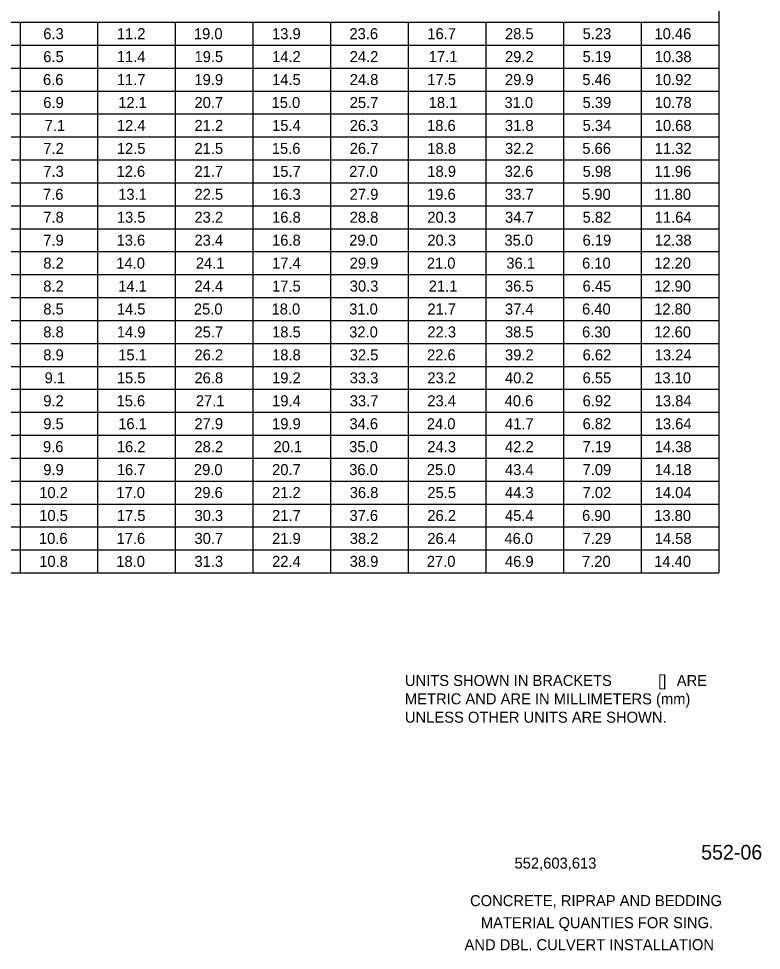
# Model space of a CAD drawing. Extents: x 49991.4 to 50047.6, y 49987.6 to 50011.4.
# Drawn here: x 50043.52 to 50047.57, y 49988.32 to 49993.4 of the extents above; entities that cross this region are included whole.
import ezdxf

# ---------------------------------------------------------------- set-up
doc = ezdxf.new("R2010")
doc.units = 0
doc.layers.add('Level 2', color=7, linetype='Continuous')

msp = doc.modelspace()

# ---------------------------------------------------------------- linework, layer by layer
at = {"layer": 'Level 2'}
for p, q in [((50047.3341, 49998.1607), (50047.3341, 49990.3807)), ((50039.4641, 49993.3807), (50047.3341, 49993.3807)), ((50043.5262, 49993.3807), (50043.5262, 49990.3807)), ((50043.9493, 49993.3807), (50043.9493, 49990.3807)), ((50044.3724, 49993.3807), (50044.3724, 49990.3807)), ((50044.7955, 49993.3807), (50044.7955, 49990.3807)), ((50045.2186, 49993.3807), (50045.2186, 49990.3807)), ((50045.6417, 49993.3807), (50045.6417, 49990.3807)), ((50046.0648, 49993.3807), (50046.0648, 49990.3807)), ((50046.4879, 49993.3807), (50046.4879, 49990.3807)), ((50046.911, 49993.3807), (50046.911, 49990.3807)), ((50039.4641, 49993.2557), (50047.3341, 49993.2557)), ((50039.4641, 49993.1307), (50047.3341, 49993.1307)), ((50039.4641, 49993.0057), (50047.3341, 49993.0057)), ((50039.4641, 49992.8807), (50047.3341, 49992.8807)), ((50039.4641, 49992.7557), (50047.3341, 49992.7557)), ((50039.4641, 49992.6307), (50047.3341, 49992.6307)), ((50039.4641, 49992.5057), (50047.3341, 49992.5057)), ((50039.4641, 49992.3807), (50047.3341, 49992.3807)), ((50039.4641, 49992.2557), (50047.3341, 49992.2557)), ((50039.4641, 49992.1307), (50047.3341, 49992.1307)), ((50039.4641, 49992.0057), (50047.3341, 49992.0057)), ((50039.4641, 49991.8807), (50047.3341, 49991.8807)), ((50039.4641, 49991.7557), (50047.3341, 49991.7557)), ((50039.4641, 49991.6307), (50047.3341, 49991.6307)), ((50039.4641, 49991.5057), (50047.3341, 49991.5057)), ((50039.4641, 49991.3807), (50047.3341, 49991.3807)), ((50039.4641, 49991.2557), (50047.3341, 49991.2557)), ((50039.4641, 49991.1307), (50047.3341, 49991.1307)), ((50039.4641, 49991.0057), (50047.3341, 49991.0057)), ((50039.4641, 49990.8807), (50047.3341, 49990.8807)), ((50039.4641, 49990.7557), (50047.3341, 49990.7557)), ((50039.4641, 49990.6307), (50047.3341, 49990.6307)), ((50039.4641, 49990.5057), (50047.3341, 49990.5057)), ((50039.4641, 49990.3807), (50047.3341, 49990.3807))]:
    msp.add_line(p, q, dxfattribs=at)

# ---------------------------------------------------------------- texts
for s, height, p in [(' 6.3', 0.06, (50043.6308, 49993.2882)), ('11.2', 0.06, (50044.0539, 49993.2882)), ('19.0', 0.06, (50044.474, 49993.2882)), ('13.9', 0.06, (50044.8999, 49993.2882)), ('23.6', 0.06, (50045.3216, 49993.2882)), ('16.7', 0.06, (50045.7463, 49993.2882)), ('28.5', 0.06, (50046.1694, 49993.2882)), ('5.23', 0.06, (50046.5925, 49993.2882)), ('10.46', 0.06, (50046.984, 49993.2882)), (' 6.5', 0.06, (50043.6308, 49993.1632)), ('11.4', 0.06, (50044.0539, 49993.1632)), ('19.5', 0.06, (50044.477, 49993.1632)), ('14.2', 0.06, (50044.9001, 49993.1632)), ('24.2', 0.06, (50045.3232, 49993.1632)), ('17.1', 0.06, (50045.7537, 49993.1632)), ('29.2', 0.06, (50046.1694, 49993.1632)), ('5.19', 0.06, (50046.5923, 49993.1632)), ('10.38', 0.06, (50046.9856, 49993.1632)), (' 6.6', 0.06, (50043.6292, 49993.0382)), ('11.7', 0.06, (50044.0539, 49993.0382)), ('19.9', 0.06, (50044.4768, 49993.0382)), ('14.5', 0.06, (50044.9001, 49993.0382)), ('24.8', 0.06, (50045.3232, 49993.0382)), ('17.5', 0.06, (50045.7463, 49993.0382)), ('29.9', 0.06, (50046.1692, 49993.0382)), ('5.46', 0.06, (50046.5909, 49993.0382)), ('10.92', 0.06, (50046.9856, 49993.0382)), (' 6.9', 0.06, (50043.6306, 49992.9132)), ('12.1', 0.06, (50044.0613, 49992.9132)), ('20.7', 0.06, (50044.477, 49992.9132)), ('15.0', 0.06, (50044.8971, 49992.9132)), ('25.7', 0.06, (50045.3232, 49992.9132)), ('18.1', 0.06, (50045.7537, 49992.9132)), ('31.0', 0.06, (50046.1664, 49992.9132)), ('5.39', 0.06, (50046.5923, 49992.9132)), ('10.78', 0.06, (50046.9856, 49992.9132)), (' 7.1', 0.06, (50043.6382, 49992.7882)), ('12.4', 0.06, (50044.0539, 49992.7882)), ('21.2', 0.06, (50044.477, 49992.7882)), ('15.4', 0.06, (50044.9001, 49992.7882)), ('26.3', 0.06, (50045.3232, 49992.7882)), ('18.6', 0.06, (50045.7447, 49992.7882)), ('31.8', 0.06, (50046.1694, 49992.7882)), ('5.34', 0.06, (50046.5925, 49992.7882)), ('10.68', 0.06, (50046.9856, 49992.7882)), (' 7.2', 0.06, (50043.6308, 49992.6632)), ('12.5', 0.06, (50044.0539, 49992.6632)), ('21.5', 0.06, (50044.477, 49992.6632)), ('15.6', 0.06, (50044.8985, 49992.6632)), ('26.7', 0.06, (50045.3232, 49992.6632)), ('18.8', 0.06, (50045.7463, 49992.6632)), ('32.2', 0.06, (50046.1694, 49992.6632)), ('5.66', 0.06, (50046.5909, 49992.6632)), ('11.32', 0.06, (50046.9856, 49992.6632)), (' 7.3', 0.06, (50043.6308, 49992.5382)), ('12.6', 0.06, (50044.0523, 49992.5382)), ('21.7', 0.06, (50044.477, 49992.5382)), ('15.7', 0.06, (50044.9001, 49992.5382)), ('27.0', 0.06, (50045.3202, 49992.5382)), ('18.9', 0.06, (50045.7461, 49992.5382)), ('32.6', 0.06, (50046.1678, 49992.5382)), ('5.98', 0.06, (50046.5925, 49992.5382)), ('11.96', 0.06, (50046.984, 49992.5382)), (' 7.6', 0.06, (50043.6292, 49992.4132)), ('13.1', 0.06, (50044.0613, 49992.4132)), ('22.5', 0.06, (50044.477, 49992.4132)), ('16.3', 0.06, (50044.9001, 49992.4132)), ('27.9', 0.06, (50045.323, 49992.4132)), ('19.6', 0.06, (50045.7447, 49992.4132)), ('33.7', 0.06, (50046.1694, 49992.4132)), ('5.90', 0.06, (50046.5895, 49992.4132)), ('11.80', 0.06, (50046.9826, 49992.4132)), (' 7.8', 0.06, (50043.6308, 49992.2882)), ('13.5', 0.06, (50044.0539, 49992.2882)), ('23.2', 0.06, (50044.477, 49992.2882)), ('16.8', 0.06, (50044.9001, 49992.2882)), ('28.8', 0.06, (50045.3232, 49992.2882)), ('20.3', 0.06, (50045.7463, 49992.2882)), ('34.7', 0.06, (50046.1694, 49992.2882)), ('5.82', 0.06, (50046.5925, 49992.2882)), ('11.64', 0.06, (50046.9856, 49992.2882)), (' 7.9', 0.06, (50043.6306, 49992.1632)), ('13.6', 0.06, (50044.0523, 49992.1632)), ('23.4', 0.06, (50044.477, 49992.1632)), ('16.8', 0.06, (50044.9001, 49992.1632)), ('29.0', 0.06, (50045.3202, 49992.1632)), ('20.3', 0.06, (50045.7463, 49992.1632)), ('35.0', 0.06, (50046.1664, 49992.1632)), ('6.19', 0.06, (50046.5923, 49992.1632)), ('12.38', 0.06, (50046.9856, 49992.1632)), (' 8.2', 0.06, (50043.6308, 49992.0382)), ('14.0', 0.06, (50044.0509, 49992.0382)), ('24.1', 0.06, (50044.4844, 49992.0382)), ('29.9', 0.06, (50045.323, 49992.0382)), ('21.0', 0.06, (50045.7433, 49992.0382)), ('36.1', 0.06, (50046.1768, 49992.0382)), ('6.10', 0.06, (50046.5895, 49992.0382)), ('12.20', 0.06, (50046.9826, 49992.0382)), ('17.4', 0.06, (50044.9001, 49992.0382)), (' 8.2', 0.06, (50043.6308, 49991.9132)), ('14.1', 0.06, (50044.0613, 49991.9132)), ('24.4', 0.06, (50044.477, 49991.9132)), ('17.5', 0.06, (50044.9001, 49991.9132)), ('30.3', 0.06, (50045.3232, 49991.9132)), ('21.1', 0.06, (50045.7537, 49991.9132)), ('36.5', 0.06, (50046.1694, 49991.9132)), ('6.45', 0.06, (50046.5925, 49991.9132)), ('12.90', 0.06, (50046.9826, 49991.9132)), (' 8.5', 0.06, (50043.6308, 49991.7882)), ('14.5', 0.06, (50044.0539, 49991.7882)), ('25.0', 0.06, (50044.474, 49991.7882)), ('18.0', 0.06, (50044.8971, 49991.7882)), ('31.0', 0.06, (50045.3202, 49991.7882)), ('21.7', 0.06, (50045.7463, 49991.7882)), ('37.4', 0.06, (50046.1694, 49991.7882)), ('6.40', 0.06, (50046.5895, 49991.7882)), ('12.80', 0.06, (50046.9826, 49991.7882)), (' 8.8', 0.06, (50043.6308, 49991.6632)), ('14.9', 0.06, (50044.0537, 49991.6632)), ('25.7', 0.06, (50044.477, 49991.6632)), ('18.5', 0.06, (50044.9001, 49991.6632)), ('32.0', 0.06, (50045.3202, 49991.6632)), ('22.3', 0.06, (50045.7463, 49991.6632)), ('38.5', 0.06, (50046.1694, 49991.6632)), ('6.30', 0.06, (50046.5895, 49991.6632)), ('12.60', 0.06, (50046.9826, 49991.6632)), (' 8.9', 0.06, (50043.6306, 49991.5382)), ('15.1', 0.06, (50044.0613, 49991.5382)), ('26.2', 0.06, (50044.477, 49991.5382)), ('18.8', 0.06, (50044.9001, 49991.5382)), ('32.5', 0.06, (50045.3232, 49991.5382)), ('22.6', 0.06, (50045.7447, 49991.5382)), ('39.2', 0.06, (50046.1694, 49991.5382)), ('6.62', 0.06, (50046.5925, 49991.5382)), ('13.24', 0.06, (50046.9856, 49991.5382)), (' 9.1', 0.06, (50043.6382, 49991.4132)), ('15.5', 0.06, (50044.0539, 49991.4132)), ('26.8', 0.06, (50044.477, 49991.4132)), ('19.2', 0.06, (50044.9001, 49991.4132)), ('33.3', 0.06, (50045.3232, 49991.4132)), ('23.2', 0.06, (50045.7463, 49991.4132)), ('40.2', 0.06, (50046.1694, 49991.4132)), ('6.55', 0.06, (50046.5925, 49991.4132)), ('13.10', 0.06, (50046.9826, 49991.4132)), (' 9.2', 0.06, (50043.6308, 49991.2882)), ('15.6', 0.06, (50044.0523, 49991.2882)), ('27.1', 0.06, (50044.4844, 49991.2882)), ('19.4', 0.06, (50044.9001, 49991.2882)), ('33.7', 0.06, (50045.3232, 49991.2882)), ('23.4', 0.06, (50045.7463, 49991.2882)), ('40.6', 0.06, (50046.1678, 49991.2882)), ('6.92', 0.06, (50046.5925, 49991.2882)), ('13.84', 0.06, (50046.9856, 49991.2882)), (' 9.5', 0.06, (50043.6308, 49991.1632)), ('16.1', 0.06, (50044.0613, 49991.1632)), ('27.9', 0.06, (50044.4768, 49991.1632)), ('19.9', 0.06, (50044.8999, 49991.1632)), ('34.6', 0.06, (50045.3216, 49991.1632)), ('24.0', 0.06, (50045.7433, 49991.1632)), ('41.7', 0.06, (50046.1694, 49991.1632)), ('6.82', 0.06, (50046.5925, 49991.1632)), ('13.64', 0.06, (50046.9856, 49991.1632)), (' 9.6', 0.06, (50043.6292, 49991.0382)), ('16.2', 0.06, (50044.0539, 49991.0382)), ('28.2', 0.06, (50044.477, 49991.0382)), ('20.1', 0.06, (50044.9075, 49991.0382)), ('35.0', 0.06, (50045.3202, 49991.0382)), ('24.3', 0.06, (50045.7463, 49991.0382)), ('42.2', 0.06, (50046.1694, 49991.0382)), ('7.19', 0.06, (50046.5923, 49991.0382)), ('14.38', 0.06, (50046.9856, 49991.0382)), (' 9.9', 0.06, (50043.6306, 49990.9132)), ('16.7', 0.06, (50044.0539, 49990.9132)), ('29.0', 0.06, (50044.474, 49990.9132)), ('20.7', 0.06, (50044.9001, 49990.9132)), ('36.0', 0.06, (50045.3202, 49990.9132)), ('25.0', 0.06, (50045.7433, 49990.9132)), ('43.4', 0.06, (50046.1694, 49990.9132)), ('7.09', 0.06, (50046.5923, 49990.9132)), ('14.18', 0.06, (50046.9856, 49990.9132)), ('10.2', 0.06, (50043.6308, 49990.7882)), ('17.0', 0.06, (50044.0509, 49990.7882)), ('29.6', 0.06, (50044.4754, 49990.7882)), ('21.2', 0.06, (50044.9001, 49990.7882)), ('36.8', 0.06, (50045.3232, 49990.7882)), ('25.5', 0.06, (50045.7463, 49990.7882)), ('44.3', 0.06, (50046.1694, 49990.7882)), ('7.02', 0.06, (50046.5925, 49990.7882)), ('14.04', 0.06, (50046.9856, 49990.7882)), ('10.5', 0.06, (50043.6308, 49990.6632)), ('17.5', 0.06, (50044.0539, 49990.6632)), ('30.3', 0.06, (50044.477, 49990.6632)), ('21.7', 0.06, (50044.9001, 49990.6632)), ('37.6', 0.06, (50045.3216, 49990.6632)), ('26.2', 0.06, (50045.7463, 49990.6632)), ('45.4', 0.06, (50046.1694, 49990.6632)), ('6.90', 0.06, (50046.5895, 49990.6632)), ('13.80', 0.06, (50046.9826, 49990.6632)), ('10.6', 0.06, (50043.6292, 49990.5382)), ('17.6', 0.06, (50044.0523, 49990.5382)), ('30.7', 0.06, (50044.477, 49990.5382)), ('21.9', 0.06, (50044.8999, 49990.5382)), ('38.2', 0.06, (50045.3232, 49990.5382)), ('26.4', 0.06, (50045.7463, 49990.5382)), ('46.0', 0.06, (50046.1664, 49990.5382)), ('7.29', 0.06, (50046.5923, 49990.5382)), ('14.58', 0.06, (50046.9856, 49990.5382)), ('10.8', 0.06, (50043.6308, 49990.4132)), ('18.0', 0.06, (50044.0509, 49990.4132)), ('31.3', 0.06, (50044.477, 49990.4132)), ('22.4', 0.06, (50044.9001, 49990.4132)), ('38.9', 0.06, (50045.323, 49990.4132)), ('27.0', 0.06, (50045.7433, 49990.4132)), ('46.9', 0.06, (50046.1692, 49990.4132)), ('7.20', 0.06, (50046.5895, 49990.4132)), ('14.40', 0.06, (50046.9826, 49990.4132)), ('UNITS SHOWN IN BRACKETS ', 0.06, (50045.624, 49989.7642)), ('[]', 0.06, (50047.004, 49989.7642)), (' ARE ', 0.06, (50047.0834, 49989.7642)), ('METRIC AND ARE IN MILLIMETERS (mm) ', 0.06, (50045.624, 49989.6642)), ('UNLESS OTHER UNITS ARE SHOWN.', 0.06, (50045.624, 49989.5642)), ('552-06', 0.08, (50047.2384, 49988.8187)), ('552,603,613', 0.06, (50046.2214, 49988.7693)), ('CONCRETE, RIPRAP AND BEDDING', 0.06, (50045.9789, 49988.5647)), ('MATERIAL QUANTIES FOR SING.', 0.06, (50046.0377, 49988.4447)), ('AND DBL. CULVERT INSTALLATION', 0.06, (50045.9489, 49988.3247))]:
    msp.add_text(s, height=height, dxfattribs=at).set_placement(p)

doc.saveas('drawing.dxf')
